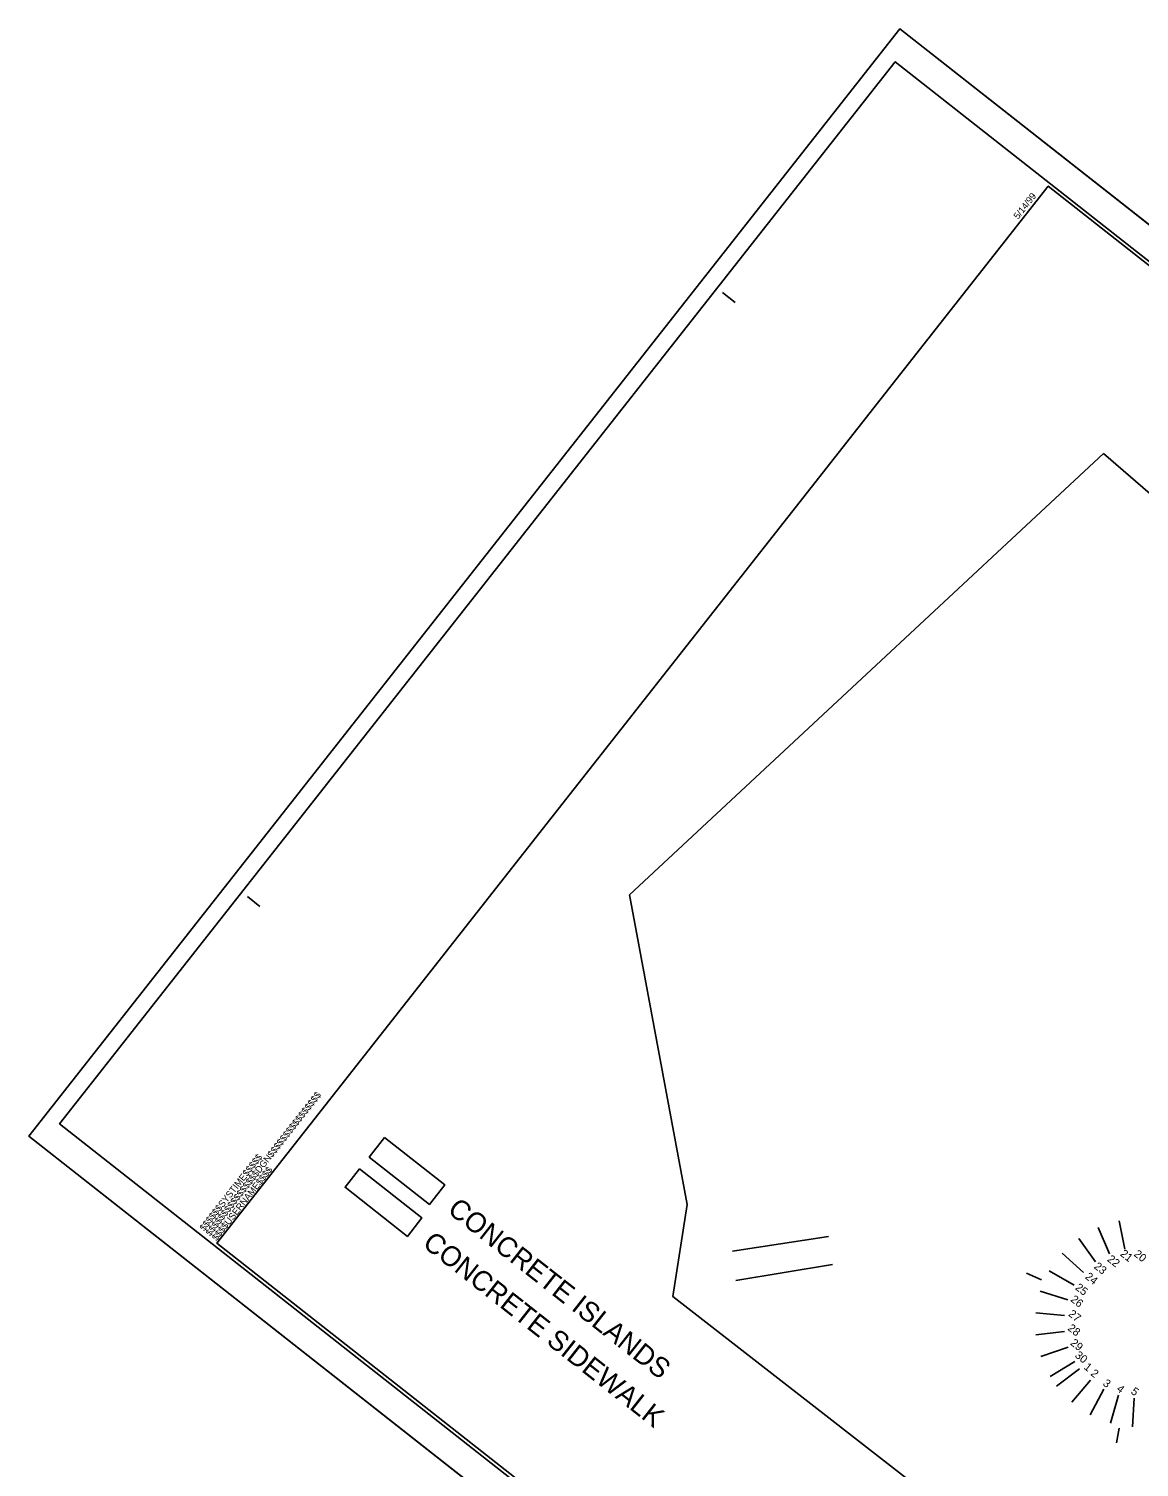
# Model space of a CAD drawing. Extents: x 556999 to 560450, y 504801 to 507732.
# Drawn here: x 556999 to 557693, y 506833 to 507732 of the extents above; entities that cross this region are included whole.
import ezdxf

# ---------------------------------------------------------------- set-up
doc = ezdxf.new("R2010")
doc.units = 0
for name, color, linetype in [('Exist Roads EOP', 7, 'Continuous'), ('Prop Conc 4in Sidewalk', 7, 'Continuous'), ('Prop Conc 5in Monolithic Surface Mount Island', 7, 'Continuous'), ('Prop Dimension', 7, 'Continuous'), ('Prop Dimension Text', 7, 'Continuous'), ('Sheet Border Standard 30in CELL', 7, 'Continuous'), ('Sheet Clip Boundary CELL', 7, 'Continuous'), ('Sheet Cutting Line CELL', 7, 'Continuous'), ('Sheet Plot Border Inside CELL', 7, 'Continuous'), ('Sheet Plot Border Outside CELL', 7, 'Continuous')]:
    doc.layers.add(name, color=color, linetype=linetype)

msp = doc.modelspace()

# ---------------------------------------------------------------- linework, layer by layer
at = {"layer": 'Exist Roads EOP'}
for p, q in [((557498.41, 506977.16), (557438.48, 506968.05)), ((557501.04, 506959.61), (557440.68, 506949.56))]:
    msp.add_line(p, q, dxfattribs=at)
at = {"layer": 'Prop Conc 4in Sidewalk'}
msp.add_lwpolyline([(557205.68, 507019.38), (557244.64, 506988.73), (557235.58, 506977.2), (557196.61, 507007.85)], close=True, dxfattribs=at)
at = {"layer": 'Prop Conc 5in Monolithic Surface Mount Island'}
msp.add_lwpolyline([(557221.3, 507039), (557258.96, 507009.39), (557249.33, 506997.15), (557211.67, 507026.76)], close=True, dxfattribs=at)
at = {"layer": 'Prop Dimension'}
for p, q in [((557673.93, 506966.22), (557666.78, 506982.74)), ((557683.46, 506969.19), (557679.96, 506986.84)), ((557665.24, 506961.31), (557654.77, 506975.95)), ((557657.78, 506954.67), (557644.46, 506966.77)), ((557651.9, 506946.61), (557636.32, 506955.62)), ((557622.09, 506954.26), (557631.45, 506950.12)), ((557647.85, 506937.49), (557630.71, 506943.01)), ((557645.81, 506927.72), (557627.9, 506929.49)), ((557645.89, 506917.73), (557628.01, 506915.69)), ((557648.07, 506907.99), (557631.02, 506902.22)), ((557652.26, 506898.94), (557636.82, 506889.69)), ((557655.24, 506894.54), (557640.94, 506883.61)), ((557662.11, 506887.3), (557650.43, 506873.6)), ((557670.35, 506881.67), (557661.83, 506865.81)), ((557679.59, 506877.91), (557674.62, 506860.61)), ((557689.43, 506876.19), (557688.22, 506858.23)), ((557678.25, 506848.22), (557679.98, 506857.28))]:
    msp.add_line(p, q, dxfattribs=at)
at = {"layer": 'Sheet Border Standard 30in CELL'}
for p, q in [((557636.37, 507632.78), (557636.37, 507632.78)), ((557432.32, 507566.79), (557440.18, 507560.61)), ((557135.61, 507189.49), (557143.47, 507183.31))]:
    msp.add_line(p, q, dxfattribs=at)
msp.add_lwpolyline([(558579, 506891.48), (557635.74, 507633.27), (557116.49, 506972.99), (558059.75, 506231.2)], close=True, dxfattribs=at)
at = {"layer": 'Sheet Clip Boundary CELL'}
msp.add_lwpolyline([(557670.21, 507466.23), (558103.06, 507091.75), (558010.57, 506993.11), (557957.23, 506919.09), (557959.37, 506915.73), (557924.17, 506870.66), (557915.94, 506859.67), (557912.12, 506855.15), (557904.86, 506850.09), (557847.72, 506801.46), (557761.69, 506715.56), (557751.89, 506695.94), (557782.23, 506664.04), (557786.18, 506640.54), (557672.55, 506724.62), (557610.32, 506776.93), (557401.38, 506939.59), (557410.24, 506997.06), (557374.28, 507190.56)], close=True, dxfattribs=at)
at = {"layer": 'Sheet Cutting Line CELL'}
for p, q in [((557543.09, 507731.58), (556999.11, 507039.85)), ((558602.06, 506898.8), (557543.09, 507731.58)), ((556999.11, 507039.85), (558058.08, 506207.07))]:
    msp.add_line(p, q, dxfattribs=at)
at = {"layer": 'Sheet Plot Border Inside CELL'}
msp.add_lwpolyline([(558588.12, 506886.9), (557540.16, 507711.03), (557018.38, 507047.54), (558066.35, 506223.41)], close=True, dxfattribs=at)
at = {"layer": 'Sheet Plot Border Outside CELL'}
msp.add_lwpolyline([(558602.06, 506898.8), (557543.09, 507731.58), (556999.11, 507039.85), (558058.08, 506207.07)], close=True, dxfattribs=at)

# ---------------------------------------------------------------- texts
at = {"layer": 'Prop Dimension'}
for s, p in [('CONCRETE ISLANDS', (557259.91, 506992.46)), ('CONCRETE SIDEWALK', (557244.33, 506971.39))]:
    msp.add_text(s, height=12.5, rotation=321.81814, dxfattribs=at).set_placement(p)
at = {"layer": 'Prop Dimension Text'}
for s, p in [('22', (557672.12, 506962.17)), ('21', (557680.23, 506965.54)), ('20', (557688.75, 506965.39)), ('23', (557663.86, 506957.66)), ('25', (557652.13, 506944.45)), ('24', (557658.33, 506951.26)), ('26', (557649.25, 506937.05)), ('27', (557647.89, 506927.95)), ('28', (557647.45, 506919.06)), ('29', (557649.11, 506909.85)), ('30', (557651.96, 506902.15)), ('1', (557657.58, 506894.79)), ('2', (557661.77, 506890.82)), ('3', (557669.38, 506884.59)), ('4', (557677.92, 506881.14)), ('5', (557686.86, 506879.49))]:
    msp.add_text(s, height=5, rotation=321.70536, dxfattribs=at).set_placement(p)
at = {"layer": 'Sheet Border Standard 30in CELL'}
for s, p in [('5/14/99', (557616.92, 507612.25)), ('$$$$$$$$$$$$$$$$DGN$$$$$$$$$$$$$$$$', (557112.41, 506977.06)), ('$$$$$$SYSTIME$$$$$', (557108.7, 506980.18)), ('$$$$USERNAME$$$$', (557116.42, 506974.01))]:
    msp.add_text(s, height=4.2, rotation=51.81814, dxfattribs=at).set_placement(p)

doc.saveas('drawing.dxf')
